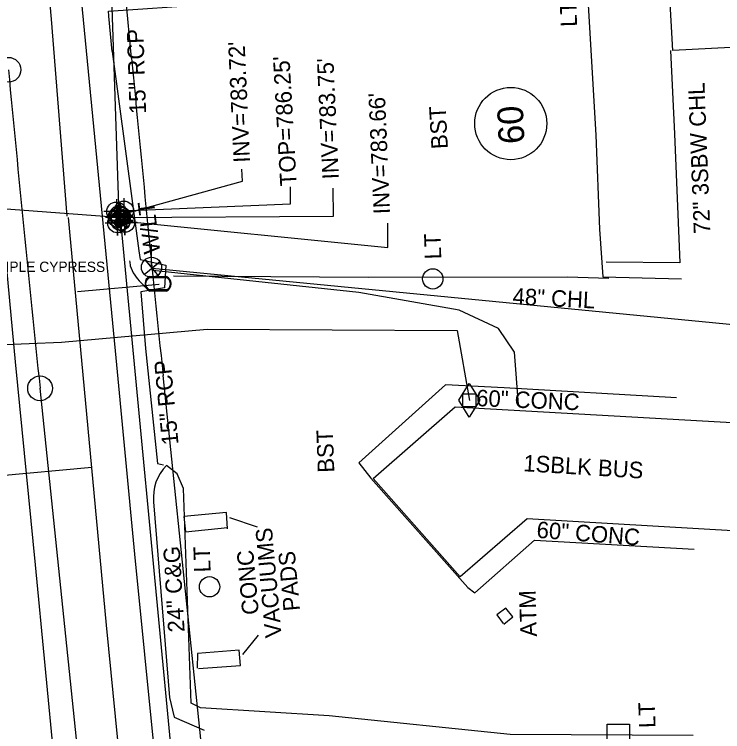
# Model space of a CAD drawing. Extents: x 1627482 to 1629573, y 760826 to 766301.
# Drawn here: x 1628290.6 to 1628462.4, y 765353.8 to 765527.6 of the extents above; entities that cross this region are included whole.
import ezdxf

# ---------------------------------------------------------------- set-up
doc = ezdxf.new("R2010")
doc.units = 0
for name, color, linetype in [('CTL Vertical Benchmark Cogo Comment', 7, 'Continuous'), ('Exist Building', 7, 'Continuous'), ('Exist Building Leader', 7, 'Continuous'), ('Exist Building Text', 7, 'Continuous'), ('Exist Horizontal Alignment', 7, 'Continuous'), ('Exist Horizontal Alignment Point', 7, 'Continuous'), ('Exist Other Culture Area Outline', 7, 'Continuous'), ('Exist Other Culture Area Outline Text', 7, 'Continuous'), ('Exist Other Culture Fence Line', 7, 'Continuous'), ('Exist Other Culture Fence Line Text', 7, 'Continuous'), ('Exist Property Corner CELL', 7, 'Continuous'), ('Exist Property Line', 7, 'Continuous'), ('Exist Property Owner Number CELL', 7, 'Continuous'), ('Exist Right of Way Line', 7, 'Continuous'), ('Exist Roads Change in Surface', 7, 'Continuous'), ('Exist Roads Curbs', 7, 'Continuous'), ('Exist Roads Curbs Text', 7, 'Continuous'), ('Exist Roads EOP', 7, 'Continuous'), ('Exist Roads EOP Text', 7, 'Continuous'), ('Exist Roads EOT', 7, 'Continuous'), ('Exist Structure Minor Catch Basin Cogo Point CELL', 7, 'Continuous'), ('Exist Structure Minor Drop Inlet', 7, 'Continuous'), ('Exist Structure Minor Drop Inlet Cogo Point CELL', 7, 'Continuous'), ('Exist Structure Minor Drop Inlet Leader', 7, 'Continuous'), ('Exist Structure Minor Drop Inlet Top Elevation', 7, 'Continuous'), ('Exist Structure Minor Pipes RCP 15 Inch', 7, 'Continuous'), ('Exist Structure Minor Pipes RCP 15 Inch Cogo Point CELL', 7, 'Continuous'), ('Exist Structure Minor Pipes RCP 15 Inch Invert', 7, 'Continuous'), ('Exist Structure Minor Pipes RCP 15 Inch Leader', 7, 'Continuous'), ('Exist Structure Minor Pipes RCP 15 Inch Text', 7, 'Continuous'), ('Exist Structure Minor Pipes RCP 18 Inch', 7, 'Continuous'), ('Exist Structure Minor Pipes RCP 18 Inch Cogo Point CELL', 7, 'Continuous'), ('Exist Structure Minor Pipes RCP 18 Inch Invert', 7, 'Continuous'), ('Exist Structure Minor Pipes RCP 18 Inch Leader', 7, 'Continuous'), ('Exist Utilities Gas Meter CELL', 7, 'Continuous'), ('Exist Utilities Gas UG Line SUE LOS B', 7, 'Continuous'), ('Exist Utilities Other Pole CELL', 7, 'Continuous'), ('Exist Utilities Other Pole Text', 7, 'Continuous'), ('Exist Utilities Other Pole With Base CELL', 7, 'Continuous'), ('Exist Utilities Other Pole With Base Text', 7, 'Continuous'), ('Exist Utilities Power Pole CELL', 7, 'Continuous'), ('Exist Utilities Power Pole Text', 7, 'Continuous'), ('Exist Utilities Power UG Cable SUE LOS B', 7, 'Continuous'), ('Exist Utilities Water Meter CELL', 7, 'Continuous'), ('Exist Utilities Water UG Line SUE LOS B', 7, 'Continuous')]:
    doc.layers.add(name, color=color, linetype=linetype)

msp = doc.modelspace()

# ---------------------------------------------------------------- linework, layer by layer
at = {"layer": 'Exist Building'}
for points in [[(1628448.62, 765549.17), (1628499.15, 765551.45), (1628500.35, 765521.45), (1628450.3, 765518.85)], [(1628377.62, 765415.12), (1628397.56, 765432.53), (1628478.93, 765427.91), (1628477.34, 765401.7), (1628415, 765405.32), (1628398.74, 765391.3)]]:
    msp.add_lwpolyline(points, close=True, dxfattribs=at)
for points in [[(1628342.34, 765402.95), (1628342.06, 765406.86), (1628331.76, 765405.95), (1628332.16, 765402.23), (1628342.28, 765403.24)], [(1628409.35, 765379.87), (1628411.5, 765381.62), (1628409.79, 765383.73), (1628407.66, 765382.11), (1628409.17, 765379.99)], [(1628335.3, 765369.07), (1628345.44, 765369.81), (1628345.18, 765373.52), (1628335.05, 765372.74), (1628334.98, 765369.13)]]:
    msp.add_lwpolyline(points, dxfattribs=at)
at = {"layer": 'Exist Building Leader'}
for p, q in [((1628342.84, 765405.68), (1628349.52, 765403.46)), ((1628346.05, 765372.51), (1628349.86, 765377.17))]:
    msp.add_line(p, q, dxfattribs=at)
at = {"layer": 'Exist Horizontal Alignment'}
msp.add_line((1628315.58, 765257.27), (1628296.86, 765437), dxfattribs=at)
msp.add_arc((1636253.8, 766265.88), 8000, 185.391427, 185.947048, dxfattribs=at)
at = {"layer": 'Exist Horizontal Alignment Point'}
for centre in [(1628289.19, 765514.2), (1628296.86, 765437)]:
    msp.add_circle(centre, 3, dxfattribs=at)
at = {"layer": 'Exist Other Culture Area Outline'}
msp.add_lwpolyline([(1628451.22, 765434.67), (1628409.42, 765437.11), (1628395.2, 765437.81), (1628374.14, 765418.92), (1628377.1, 765415.23), (1628400.61, 765388.69), (1628402.3, 765387.46), (1628416.78, 765400.22), (1628455.52, 765397.98)], dxfattribs=at)
at = {"layer": 'Exist Other Culture Fence Line'}
for points in [[(1628449.72, 765518.91), (1628450.76, 765498.69), (1628451.98, 765467.43), (1628434.16, 765467.54)], [(1628329.26, 765464.24), (1628376.45, 765463.96), (1628424.78, 765464.04), (1628434.77, 765463.67)]]:
    msp.add_lwpolyline(points, dxfattribs=at)
at = {"layer": 'Exist Property Corner CELL'}
msp.add_line((1628324.03, 765466.13), (1628324.03, 765466.13), dxfattribs=at)
msp.add_lwpolyline([(1628322.1, 765464.54), (1628325.96, 765467.72), (1628324.03, 765466.13), (1628322.44, 765468.06), (1628325.62, 765464.2)], dxfattribs=at)
at = {"layer": 'Exist Property Line'}
msp.add_lwpolyline([(1628324.03, 765466.13), (1628556.59, 765443.58)], dxfattribs=at)
at = {"layer": 'Exist Property Owner Number CELL'}
msp.add_circle((1628411.01, 765501.16), 8.75, dxfattribs=at)
at = {"layer": 'Exist Right of Way Line'}
for p, q in [((1628319.06, 765517.02), (1628312.14, 765590.34)), ((1628345.42, 765260.38), (1628326.7, 765440.11))]:
    msp.add_line(p, q, dxfattribs=at)
msp.add_arc((1636253.8, 766265.88), 7970, 185.391427, 185.947048, dxfattribs=at)
at = {"layer": 'Exist Roads Change in Surface'}
for points in [[(1628314.35, 765518.63), (1628313.56, 765527.21)], [(1628314.35, 765518.63), (1628320.83, 765470.29)], [(1628321.28, 765460.4), (1628322.46, 765446.66), (1628325.31, 765418.75), (1628326.76, 765418.44)]]:
    msp.add_lwpolyline(points, dxfattribs=at)
at = {"layer": 'Exist Roads Curbs'}
for p, q in [((1628318.57, 765467.9), (1628318.56, 765467.89)), ((1628322.98, 765461.01), (1628322.96, 765461)), ((1628327.51, 765418.3), (1628327.51, 765418.3))]:
    msp.add_line(p, q, dxfattribs=at)
msp.add_lwpolyline([(1628324.41, 765409.45), (1628328.26, 765362.08), (1628329.39, 765357.28), (1628336.62, 765354.11)], dxfattribs=at)
msp.add_ellipse((1628335.28, 765410.6), major_axis=(-2.1, -10.75), ratio=0.998033, start_param=4.126205, end_param=5.011153, dxfattribs=at)
msp.add_spline([(1628318.56, 765467.89), (1628318.74, 765466.71), (1628319.81, 765464.44), (1628322.98, 765461.01)], degree=3, dxfattribs=at)
at = {"layer": 'Exist Roads EOP'}
msp.add_line((1628330.07, 765416.23), (1628327.51, 765418.3), dxfattribs=at)
for points in [[(1628313.56, 765527.24), (1628313.45, 765528.44), (1628337.13, 765530.05), (1628344.34, 765531.22), (1628344.88, 765531.43), (1628348.38, 765529.81), (1628395.48, 765532.47), (1628429.55, 765534.14), (1628431.63, 765498.39), (1628432.57, 765475.59), (1628433.34, 765464.02), (1628452.44, 765463.49)], [(1628320.83, 765470.29), (1628321.11, 765468.23), (1628327.35, 765466.87), (1628327, 765461.36), (1628321.28, 765460.4)], [(1628335.79, 765359.53), (1628333.51, 765360.67), (1628331.65, 765412.68), (1628330.07, 765416.23)], [(1628455.23, 765352.81), (1628410.86, 765353.09), (1628366.98, 765357.63), (1628335.79, 765359.53)]]:
    msp.add_lwpolyline(points, dxfattribs=at)
at = {"layer": 'Exist Roads EOT'}
for points in [[(1628333.52, 765248.4), (1628329.4, 765298.18), (1628324.72, 765348.12), (1628319.83, 765396.83), (1628315.15, 765446.04), (1628310.38, 765495.44), (1628305.6, 765544.74), (1628300.53, 765594.55), (1628297.28, 765629.36), (1628296.07, 765643.72), (1628291.37, 765692.86), (1628286.71, 765742.17), (1628281.97, 765791.57), (1628277.28, 765840.65), (1628272.47, 765890.08), (1628267.44, 765941.93), (1628262.71, 765991.13), (1628257.98, 766041.68), (1628253.31, 766091.45), (1628248.62, 766139.51)], [(1628321.8, 765097.93), (1628317.82, 765147.67), (1628313.79, 765197.09), (1628309.5, 765246.44), (1628305.25, 765296.01), (1628300.47, 765345.4), (1628295.75, 765394.23), (1628290.92, 765443.38), (1628286.2, 765493), (1628281.48, 765542.67), (1628276.9, 765591.66), (1628272.08, 765640.85), (1628267.39, 765690.37), (1628262.64, 765739.28), (1628257.97, 765789.11), (1628253.23, 765838.22), (1628248.39, 765887.64), (1628243.39, 765938.8), (1628238.58, 765988.56), (1628233.82, 766039.14), (1628229.1, 766088.8), (1628224.69, 766136.81)]]:
    msp.add_lwpolyline(points, dxfattribs=at)
at = {"layer": 'Exist Structure Minor Catch Basin Cogo Point CELL'}
msp.add_lwpolyline([(1628313.38, 765478.57), (1628319.38, 765478.57), (1628316.38, 765478.57), (1628316.38, 765481.57), (1628316.38, 765475.57)], dxfattribs=at)
msp.add_circle((1628316.38, 765478.57), 2.34, dxfattribs=at)
at = {"layer": 'Exist Structure Minor Drop Inlet'}
msp.add_lwpolyline([(1628315.36, 765479.81), (1628317.2, 765480.05), (1628317.45, 765477.15), (1628315.62, 765477.03)], close=True, dxfattribs=at)
at = {"layer": 'Exist Structure Minor Drop Inlet Cogo Point CELL'}
for points in [[(1628317.2, 765483.05), (1628317.2, 765477.05), (1628317.2, 765480.05), (1628320.2, 765480.05), (1628314.2, 765480.05)], [(1628315.36, 765482.81), (1628315.36, 765476.81), (1628315.36, 765479.81), (1628318.36, 765479.81), (1628312.36, 765479.81)], [(1628315.62, 765480.03), (1628315.62, 765474.03), (1628315.62, 765477.03), (1628318.62, 765477.03), (1628312.62, 765477.03)], [(1628317.45, 765480.15), (1628317.45, 765474.15), (1628317.45, 765477.15), (1628320.45, 765477.15), (1628314.45, 765477.15)]]:
    msp.add_lwpolyline(points, dxfattribs=at)
for centre in [(1628315.36, 765479.81), (1628317.2, 765480.05), (1628315.62, 765477.03), (1628317.45, 765477.15)]:
    msp.add_circle(centre, 2.34, dxfattribs=at)
at = {"layer": 'Exist Structure Minor Drop Inlet Leader'}
msp.add_lwpolyline([(1628317.2, 765480.05), (1628357.61, 765481.71), (1628357.57, 765485.85)], dxfattribs=at)
at = {"layer": 'Exist Structure Minor Pipes RCP 15 Inch'}
for p, q in [((1628316.06, 765478.93), (1628311.28, 765620.52)), ((1628338.26, 765249.55), (1628316.42, 765477.58))]:
    msp.add_line(p, q, dxfattribs=at)
at = {"layer": 'Exist Structure Minor Pipes RCP 15 Inch Cogo Point CELL'}
for points in [[(1628316.06, 765481.93), (1628316.06, 765475.93), (1628316.06, 765478.93), (1628319.06, 765478.93), (1628313.06, 765478.93)], [(1628316.39, 765481.71), (1628316.39, 765475.71), (1628316.39, 765478.71), (1628319.39, 765478.71), (1628313.39, 765478.71)], [(1628316.36, 765480.69), (1628316.36, 765474.69), (1628316.36, 765477.69), (1628319.36, 765477.69), (1628313.36, 765477.69)], [(1628316.42, 765480.58), (1628316.42, 765474.58), (1628316.42, 765477.58), (1628319.42, 765477.58), (1628313.42, 765477.58)]]:
    msp.add_lwpolyline(points, dxfattribs=at)
for centre in [(1628316.06, 765478.93), (1628316.36, 765477.69), (1628316.39, 765478.71), (1628316.42, 765477.58)]:
    msp.add_circle(centre, 2.34, dxfattribs=at)
at = {"layer": 'Exist Structure Minor Pipes RCP 15 Inch Leader'}
for points in [[(1628316.06, 765478.93), (1628345.97, 765487.24), (1628345.83, 765490.15)], [(1628316.42, 765477.58), (1628381.16, 765471.12), (1628381.17, 765477)]]:
    msp.add_lwpolyline(points, dxfattribs=at)
at = {"layer": 'Exist Structure Minor Pipes RCP 18 Inch'}
msp.add_line((1628315.71, 765478.37), (1628228.56, 765485.07), dxfattribs=at)
at = {"layer": 'Exist Structure Minor Pipes RCP 18 Inch Cogo Point CELL'}
msp.add_lwpolyline([(1628315.71, 765481.37), (1628315.71, 765475.37), (1628315.71, 765478.37), (1628318.71, 765478.37), (1628312.71, 765478.37)], dxfattribs=at)
msp.add_circle((1628315.71, 765478.37), 2.34, dxfattribs=at)
at = {"layer": 'Exist Structure Minor Pipes RCP 18 Inch Leader'}
msp.add_lwpolyline([(1628315.71, 765478.37), (1628368, 765478.74), (1628367.97, 765485.48)], dxfattribs=at)
at = {"layer": 'Exist Utilities Gas Meter CELL'}
msp.add_line((1628400.96, 765434.09), (1628400.96, 765434.09), dxfattribs=at)
for points in [[(1628398.42, 765434.09), (1628400.96, 765438.2), (1628403.5, 765434.09), (1628400.96, 765429.98), (1628398.42, 765434.09)], [(1628399.38, 765435.63), (1628402.53, 765435.63), (1628402.53, 765432.52), (1628399.38, 765432.52), (1628399.38, 765435.63)]]:
    msp.add_lwpolyline(points, dxfattribs=at)
at = {"layer": 'Exist Utilities Gas UG Line SUE LOS B'}
msp.add_lwpolyline([(1628278.43, 765447.25), (1628302.09, 765448.15), (1628337.35, 765451.29), (1628398.04, 765451.01), (1628400.98, 765434.02)], dxfattribs=at)
at = {"layer": 'Exist Utilities Other Pole CELL'}
for centre in [(1628392.1, 765463.52), (1628337.97, 765388.89)]:
    msp.add_circle(centre, 2.46, dxfattribs=at)
at = {"layer": 'Exist Utilities Other Pole With Base CELL'}
msp.add_lwpolyline([(1628434.39, 765355.58), (1628439.79, 765355.58), (1628439.79, 765350.18), (1628434.39, 765350.18), (1628434.39, 765355.58)], dxfattribs=at)
at = {"layer": 'Exist Utilities Power Pole CELL'}
for q in [(1628323.9, 765471.94), (1628323.9, 765466.32)]:
    msp.add_line((1628323.9, 765466.32), q, dxfattribs=at)
msp.add_circle((1628323.9, 765466.32), 2.45, dxfattribs=at)
at = {"layer": 'Exist Utilities Power UG Cable SUE LOS B'}
msp.add_lwpolyline([(1628412.89, 765433.07), (1628411.95, 765445.78), (1628408, 765451.5), (1628398.54, 765455.95), (1628374.19, 765460.24), (1628324.2, 765465.58)], dxfattribs=at)
at = {"layer": 'Exist Utilities Water Meter CELL'}
for p, q in [((1628325.47, 765462.39), (1628325.47, 765462.39)), ((1628325.49, 765462.25), (1628325.49, 765462.25))]:
    msp.add_line(p, q, dxfattribs=at)
for points in [[(1628323.43, 765464.09), (1628327.51, 765464.09)], [(1628323.43, 765463.95), (1628327.51, 765463.95)], [(1628323.45, 765463.95), (1628327.53, 765463.95)], [(1628323.45, 765463.82), (1628327.53, 765463.82)], [(1628327.51, 765460.83), (1628323.41, 765460.83)], [(1628327.51, 765460.69), (1628323.41, 765460.69)], [(1628327.53, 765460.69), (1628323.43, 765460.69)], [(1628327.53, 765460.55), (1628323.43, 765460.55)]]:
    msp.add_lwpolyline(points, dxfattribs=at)
for centre, radius, start, end in [((1628324.17, 765462.38), 1.86, 113.178, 245.9794), ((1628324.18, 765462.25), 1.86, 113.178, 245.9794), ((1628324.18, 765462.38), 1.73, 115.3009, 243.7824), ((1628324.19, 765462.25), 1.73, 115.3009, 243.7824), ((1628326.77, 765462.39), 1.86, 293.6483, 66.3084), ((1628326.78, 765462.39), 1.73, 295.1272, 64.8728), ((1628326.78, 765462.25), 1.86, 293.6483, 66.3084), ((1628326.79, 765462.25), 1.73, 295.1272, 64.8728)]:
    msp.add_arc(centre, radius, start, end, dxfattribs=at)
at = {"layer": 'Exist Utilities Water UG Line SUE LOS B'}
for p, q in [((1628325.72, 765462.17), (1628305.91, 765460.39)), ((1628266.97, 765413.97), (1628309.41, 765417.92))]:
    msp.add_line(p, q, dxfattribs=at)
for points in [[(1628303.42, 765478.68), (1628299.6, 765526.49), (1628293.92, 765590.89)], [(1628407.24, 763655.16), (1628402.4, 763754.94), (1628399.06, 763856.51), (1628396.12, 763915.33), (1628393.3, 763992.46), (1628390.7, 764066.34), (1628386.72, 764168.39), (1628382.56, 764256.29), (1628378.23, 764373.67), (1628375.54, 764455.63), (1628372.03, 764542.25), (1628370.17, 764583.36), (1628366.9, 764671.42), (1628365.27, 764739.23), (1628362.16, 764808.05), (1628361.5, 764823.25), (1628356.13, 764896.21), (1628352.11, 764986.77), (1628341.94, 765081.92), (1628331.48, 765195.63), (1628321.82, 765290.23), (1628312.98, 765379.55), (1628303.79, 765478.36)]]:
    msp.add_lwpolyline(points, dxfattribs=at)

# ---------------------------------------------------------------- texts
at = {"layer": 'CTL Vertical Benchmark Cogo Comment'}
msp.add_text('BENCHTIE SET IN TRIPLE CYPRESS', height=2.5, dxfattribs=at).set_placement((1628254.5, 765465.2))
at = {"layer": 'Exist Building Text'}
for s, rotation, p in [('1SBLK BUS', 356.4422, (1628413.97, 765416.91)), ('VACUUMS', 95.1708, (1628355.48, 765376.71)), ('CONC', 95.1708, (1628349.94, 765382.28)), ('PADS', 95.1708, (1628359.92, 765383.18)), ('ATM', 91.7713, (1628417.35, 765376.83))]:
    msp.add_text(s, height=4, rotation=rotation, dxfattribs=at).set_placement(p)
at = {"layer": 'Exist Other Culture Area Outline Text'}
for rotation, p in [(357.6395, (1628402.56, 765432.69)), (355.6427, (1628417.17, 765400.77))]:
    msp.add_text('60" CONC', height=4, rotation=rotation, dxfattribs=at).set_placement(p)
at = {"layer": 'Exist Other Culture Fence Line Text'}
for s, rotation, p in [('72" 3SBW CHL', 92.2353, (1628459.42, 765474.51)), ('48" CHL', 357.101, (1628411.38, 765457.34))]:
    msp.add_text(s, height=4, rotation=rotation, dxfattribs=at).set_placement(p)
at = {"layer": 'Exist Property Owner Number CELL'}
msp.add_text('60', height=6.25, rotation=92.6915, dxfattribs=at).set_placement((1628414.36, 765496.35))
at = {"layer": 'Exist Roads Curbs Text'}
msp.add_text('24" C&G', height=4, rotation=93.3446, dxfattribs=at).set_placement((1628331.93, 765377.98))
at = {"layer": 'Exist Roads EOP Text'}
for rotation, p in [(93.3325, (1628395.79, 765495.1)), (92.0115, (1628368.23, 765416.61))]:
    msp.add_text('BST', height=4, rotation=rotation, dxfattribs=at).set_placement(p)
at = {"layer": 'Exist Structure Minor Drop Inlet Top Elevation'}
msp.add_text("TOP=786.25'", height=4, rotation=93.27, dxfattribs=at).set_placement((1628359.12, 765486.14))
at = {"layer": 'Exist Structure Minor Pipes RCP 15 Inch Invert'}
for s, rotation, p in [("INV=783.72'", 92.6184, (1628347.8, 765491.77)), ("INV=783.66'", 92.4673, (1628381.75, 765479.29))]:
    msp.add_text(s, height=4, rotation=rotation, dxfattribs=at).set_placement(p)
at = {"layer": 'Exist Structure Minor Pipes RCP 15 Inch Text'}
for rotation, p in [(91.9339, (1628322.59, 765503.54)), (95.4723, (1628330.46, 765423.46))]:
    msp.add_text('15" RCP', height=4, rotation=rotation, dxfattribs=at).set_placement(p)
at = {"layer": 'Exist Structure Minor Pipes RCP 18 Inch Invert'}
msp.add_text("INV=783.75'", height=4, rotation=92.6305, dxfattribs=at).set_placement((1628369.34, 765487.75))
at = {"layer": 'Exist Utilities Other Pole Text'}
for p in [(1628427.1, 765524.67), (1628394.17, 765468.33), (1628338.23, 765392.44)]:
    msp.add_text('LT', height=4, rotation=91.7713, dxfattribs=at).set_placement(p)
at = {"layer": 'Exist Utilities Other Pole With Base Text'}
msp.add_text('LT', height=4, rotation=91.7713, dxfattribs=at).set_placement((1628446.13, 765354.72))
at = {"layer": 'Exist Utilities Power Pole Text'}
msp.add_text('W/LT', height=4, rotation=97.0142, dxfattribs=at).set_placement((1628326.04, 765469.84))

doc.saveas('drawing.dxf')
